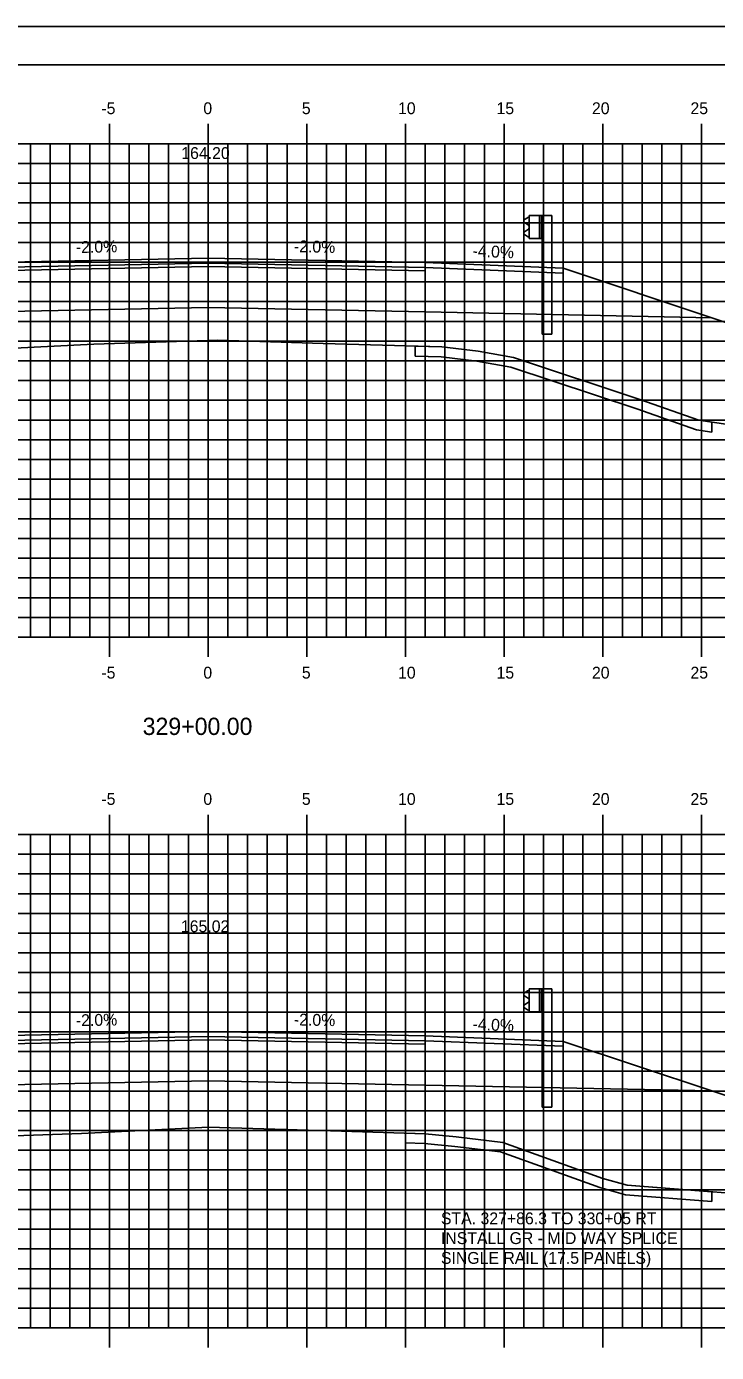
# Model space of a CAD drawing. Extents: x 1140981 to 1141151, y 608981 to 609091.
# Drawn here: x 1141054.6 to 1141089.5, y 609024.1 to 609091.3 of the extents above; entities that cross this region are included whole.
import ezdxf

# ---------------------------------------------------------------- set-up
doc = ezdxf.new("R2010")
doc.units = 0
for name, color, linetype in [('ANNOTATION', 7, 'Continuous'), ('BORDER', 7, 'Continuous'), ('D_Guardrail_Beam_Rt', 7, 'Continuous'), ('D_Guardrail_ConcBarrier', 7, 'Continuous'), ('D_Roadway_Centerline', 7, 'Continuous'), ('D_Roadway_Centerline_Text', 7, 'Continuous'), ('D_Roadway_Edge_Shoulder', 7, 'Continuous'), ('D_Roadway_Edge_TW', 7, 'Continuous'), ('D_Roadway_Pavement', 7, 'Continuous'), ('D_Roadway_SlopeLines', 7, 'Continuous'), ('D_Roadway_SubGrade', 7, 'Continuous'), ('H_V ANNOTATION', 7, 'Continuous'), ('MAJOR', 7, 'Continuous'), ('MINOR', 7, 'Continuous'), ('PLOT BOUNDARY', 7, 'Continuous'), ('S_Roadway_Centerline', 7, 'Continuous'), ('SHADING', 7, 'Continuous')]:
    doc.layers.add(name, color=color, linetype=linetype)

msp = doc.modelspace()

# ---------------------------------------------------------------- linework, layer by layer
for points in [[(1141018.694, 609070.301), (1141034.295, 609075.501), (1141037.295, 609076.501), (1141044.764, 609078.991), (1141044.765, 609078.991), (1141052.758, 609079.311), (1141063.758, 609079.531), (1141074.758, 609079.311), (1141081.758, 609079.031), (1141089.29, 609076.52), (1141092.29, 609075.52), (1141108.295, 609070.185)], [(1141015.324, 609031.014), (1141031.055, 609036.258), (1141034.055, 609037.258), (1141041.302, 609039.673), (1141041.303, 609039.673), (1141052.758, 609040.132), (1141063.758, 609040.352), (1141074.758, 609040.132), (1141081.758, 609039.852), (1141089.29, 609037.341), (1141092.29, 609036.341), (1141104.882, 609032.144)]]:
    msp.add_lwpolyline(points)
at = {"layer": 'BORDER'}
msp.add_lwpolyline([(1140988.758, 608984.335), (1141148.758, 608984.335), (1141148.758, 609089.335), (1140988.758, 609089.335)], close=True, dxfattribs=at)
at = {"layer": 'D_Guardrail_Beam_Rt'}
for p, q in [((1141079.939, 609081.59), (1141079.795, 609081.49)), ((1141079.795, 609081.347), (1141079.99, 609081.21)), ((1141080.029, 609081.611), (1141079.954, 609081.596)), ((1141079.99, 609081.011), (1141079.795, 609080.875)), ((1141079.795, 609080.732), (1141079.939, 609080.632)), ((1141079.954, 609080.626), (1141080.029, 609080.611)), ((1141080.024, 609081.146), (1141080.024, 609081.076)), ((1141079.938, 609042.411), (1141079.795, 609042.311)), ((1141080.028, 609042.432), (1141079.954, 609042.417)), ((1141079.795, 609042.168), (1141079.99, 609042.031)), ((1141079.99, 609041.832), (1141079.795, 609041.696)), ((1141080.024, 609041.967), (1141080.024, 609041.897)), ((1141079.795, 609041.553), (1141079.938, 609041.453)), ((1141079.954, 609041.447), (1141080.028, 609041.432))]:
    msp.add_line(p, q, dxfattribs=at)
for centre, major_axis, start_param, end_param in [((1141079.845, 609081.418), (-0.0877, 0), 5.323254, 7.243116), ((1141079.962, 609081.556), (-0.0417, 0), 4.907132, 5.323254), ((1141079.945, 609081.146), (0.0789, 0), 0, 0.959931), ((1141079.845, 609080.804), (-0.0877, 0), 5.323254, 7.243116), ((1141079.962, 609080.666), (-0.0417, 0), 0.959931, 1.376053), ((1141079.945, 609081.076), (0.0789, 0), 5.323254, 6.283185), ((1141079.845, 609042.239), (-0.0877, 0), 5.323254, 7.243116), ((1141079.962, 609042.377), (-0.0417, 0), 4.907132, 5.323254), ((1141079.845, 609041.625), (-0.0877, 0), 5.323254, 7.243116), ((1141079.945, 609041.967), (0.0789, 0), 0, 0.959931), ((1141079.945, 609041.897), (0.0789, 0), 5.323254, 6.283185), ((1141079.962, 609041.487), (-0.0417, 0), 0.959931, 1.376053)]:
    msp.add_ellipse(centre, major_axis=major_axis, ratio=0.995501, start_param=start_param, end_param=end_param, dxfattribs=at)
at = {"layer": 'D_Guardrail_ConcBarrier'}
for p, q in [((1141080.029, 609081.694), (1141080.716, 609081.694)), ((1141080.029, 609080.528), (1141080.029, 609081.694)), ((1141080.549, 609081.694), (1141080.549, 609080.528)), ((1141080.654, 609081.694), (1141080.654, 609080.528)), ((1141080.716, 609081.694), (1141081.187, 609081.694)), ((1141080.716, 609081.694), (1141080.716, 609080.528)), ((1141081.187, 609081.694), (1141081.187, 609075.694)), ((1141080.716, 609080.528), (1141080.029, 609080.528)), ((1141080.695, 609075.694), (1141080.695, 609080.528)), ((1141080.695, 609075.694), (1141081.187, 609075.694)), ((1141080.028, 609042.515), (1141080.716, 609042.515)), ((1141080.028, 609041.349), (1141080.028, 609042.515)), ((1141080.549, 609042.515), (1141080.549, 609041.349)), ((1141080.653, 609042.515), (1141080.653, 609041.349)), ((1141080.716, 609042.515), (1141081.187, 609042.515)), ((1141080.716, 609042.515), (1141080.716, 609041.349)), ((1141081.187, 609042.515), (1141081.187, 609036.515)), ((1141080.716, 609041.349), (1141080.028, 609041.349)), ((1141080.695, 609036.515), (1141080.695, 609041.349)), ((1141080.695, 609036.515), (1141081.187, 609036.515))]:
    msp.add_line(p, q, dxfattribs=at)
at = {"layer": 'D_Roadway_Edge_Shoulder'}
for points in [[(1141074.758, 609079.311), (1141081.758, 609079.031), (1141081.758, 609078.781), (1141074.758, 609079.061)], [(1141074.758, 609040.132), (1141081.758, 609039.852), (1141081.758, 609039.602), (1141074.758, 609039.882)]]:
    msp.add_lwpolyline(points, close=True, dxfattribs=at)
at = {"layer": 'D_Roadway_Edge_TW'}
for points in [[(1141052.758, 609079.061), (1141052.758, 609079.311), (1141063.758, 609079.531), (1141074.758, 609079.311), (1141074.758, 609079.061), (1141063.758, 609079.281)], [(1141052.758, 609039.882), (1141052.758, 609040.132), (1141063.758, 609040.352), (1141074.758, 609040.132), (1141074.758, 609039.882), (1141063.758, 609040.102)]]:
    msp.add_lwpolyline(points, close=True, dxfattribs=at)
at = {"layer": 'D_Roadway_Pavement'}
for points in [[(1141052.758, 609078.894), (1141052.758, 609079.061), (1141063.758, 609079.281), (1141074.758, 609079.061), (1141074.758, 609078.894), (1141063.758, 609079.114)], [(1141052.758, 609039.715), (1141052.758, 609039.882), (1141063.758, 609040.102), (1141074.758, 609039.882), (1141074.758, 609039.715), (1141063.758, 609039.935)]]:
    msp.add_lwpolyline(points, close=True, dxfattribs=at)
at = {"layer": 'D_Roadway_SlopeLines'}
for p, q in [((1141074.255, 609075.079), (1141074.255, 609074.579)), ((1141089.29, 609071.232), (1141089.29, 609070.727)), ((1141073.758, 609035.204), (1141073.758, 609034.704)), ((1141089.29, 609032.23), (1141089.29, 609031.736))]:
    msp.add_line(p, q, dxfattribs=at)
for points in [[(1141089.29, 609076.52), (1141092.29, 609075.52)], [(1141074.255, 609074.579), (1141075.567, 609074.54), (1141077.372, 609074.326), (1141079.104, 609074.012), (1141085.486, 609071.91), (1141088.511, 609070.842), (1141089.29, 609070.727)], [(1141089.29, 609037.341), (1141092.29, 609036.341)], [(1141073.758, 609034.711), (1141074.732, 609034.681), (1141076.268, 609034.527), (1141078.578, 609034.254), (1141083.608, 609032.442), (1141084.913, 609032.074), (1141089.29, 609031.736)]]:
    msp.add_lwpolyline(points, dxfattribs=at)
at = {"layer": 'D_Roadway_SubGrade'}
for points in [[(1141052.758, 609076.811), (1141052.758, 609078.894), (1141063.758, 609079.114), (1141074.758, 609078.894), (1141074.758, 609076.811), (1141063.758, 609077.031)], [(1141074.758, 609078.894), (1141074.758, 609079.061), (1141081.758, 609078.781), (1141081.758, 609079.031), (1141081.758, 609079.031), (1141089.29, 609076.52), (1141074.758, 609076.811)], [(1141052.758, 609037.632), (1141052.758, 609039.715), (1141063.758, 609039.935), (1141074.758, 609039.715), (1141074.758, 609037.632), (1141063.758, 609037.852)], [(1141074.758, 609039.715), (1141074.758, 609039.882), (1141081.758, 609039.602), (1141081.758, 609039.852), (1141081.758, 609039.852), (1141089.29, 609037.341), (1141074.758, 609037.632)]]:
    msp.add_lwpolyline(points, close=True, dxfattribs=at)
at = {"layer": 'MAJOR'}
for p, q in [((1141058.758, 609086.337), (1141058.758, 609085.335)), ((1141063.758, 609086.337), (1141063.758, 609085.335)), ((1141068.758, 609086.337), (1141068.758, 609085.335)), ((1141073.758, 609086.337), (1141073.758, 609085.335)), ((1141078.758, 609086.337), (1141078.758, 609085.335)), ((1141083.758, 609086.337), (1141083.758, 609085.335)), ((1141088.758, 609086.337), (1141088.758, 609085.335)), ((1140993.758, 609085.335), (1141133.758, 609085.335)), ((1140993.758, 609085.335), (1141133.758, 609085.335)), ((1141058.758, 609060.335), (1141058.758, 609085.335)), ((1141063.758, 609060.335), (1141063.758, 609085.335)), ((1141068.758, 609060.335), (1141068.758, 609085.335)), ((1141073.758, 609060.335), (1141073.758, 609085.335)), ((1141078.758, 609060.335), (1141078.758, 609085.335)), ((1141083.758, 609060.335), (1141083.758, 609085.335)), ((1141088.758, 609060.335), (1141088.758, 609085.335)), ((1140993.758, 609080.335), (1141133.758, 609080.335)), ((1140993.758, 609075.335), (1141133.758, 609075.335)), ((1140993.758, 609070.335), (1141133.758, 609070.335)), ((1140993.758, 609065.335), (1141133.758, 609065.335)), ((1140993.758, 609060.335), (1141133.758, 609060.335)), ((1140993.758, 609060.335), (1141133.758, 609060.335)), ((1141058.758, 609059.333), (1141058.758, 609060.335)), ((1141063.758, 609059.333), (1141063.758, 609060.335)), ((1141068.758, 609059.333), (1141068.758, 609060.335)), ((1141073.758, 609059.333), (1141073.758, 609060.335)), ((1141078.758, 609059.333), (1141078.758, 609060.335)), ((1141083.758, 609059.333), (1141083.758, 609060.335)), ((1141088.758, 609059.333), (1141088.758, 609060.335)), ((1141058.758, 609051.337), (1141058.758, 609050.335)), ((1141063.758, 609051.337), (1141063.758, 609050.335)), ((1141068.758, 609051.337), (1141068.758, 609050.335)), ((1141073.758, 609051.337), (1141073.758, 609050.335)), ((1141078.758, 609051.337), (1141078.758, 609050.335)), ((1141083.758, 609051.337), (1141083.758, 609050.335)), ((1141088.758, 609051.337), (1141088.758, 609050.335)), ((1140993.758, 609050.335), (1141133.758, 609050.335)), ((1140993.758, 609050.335), (1141133.758, 609050.335)), ((1141058.758, 609025.335), (1141058.758, 609050.335)), ((1141063.758, 609025.335), (1141063.758, 609050.335)), ((1141068.758, 609025.335), (1141068.758, 609050.335)), ((1141073.758, 609025.335), (1141073.758, 609050.335)), ((1141078.758, 609025.335), (1141078.758, 609050.335)), ((1141083.758, 609025.335), (1141083.758, 609050.335)), ((1141088.758, 609025.335), (1141088.758, 609050.335)), ((1140993.758, 609045.335), (1141133.758, 609045.335)), ((1140993.758, 609040.335), (1141133.758, 609040.335)), ((1140993.758, 609035.335), (1141133.758, 609035.335)), ((1140993.758, 609030.335), (1141133.758, 609030.335)), ((1140993.758, 609025.335), (1141133.758, 609025.335)), ((1140993.758, 609025.335), (1141133.758, 609025.335)), ((1141058.758, 609024.333), (1141058.758, 609025.335)), ((1141063.758, 609024.333), (1141063.758, 609025.335)), ((1141068.758, 609024.333), (1141068.758, 609025.335)), ((1141073.758, 609024.333), (1141073.758, 609025.335)), ((1141078.758, 609024.333), (1141078.758, 609025.335)), ((1141083.758, 609024.333), (1141083.758, 609025.335)), ((1141088.758, 609024.333), (1141088.758, 609025.335))]:
    msp.add_line(p, q, dxfattribs=at)
at = {"layer": 'MINOR'}
for p, q in [((1141054.758, 609060.335), (1141054.758, 609085.335)), ((1141055.758, 609060.335), (1141055.758, 609085.335)), ((1141056.758, 609060.335), (1141056.758, 609085.335)), ((1141057.758, 609060.335), (1141057.758, 609085.335)), ((1141059.758, 609060.335), (1141059.758, 609085.335)), ((1141060.758, 609060.335), (1141060.758, 609085.335)), ((1141061.758, 609060.335), (1141061.758, 609085.335)), ((1141062.758, 609060.335), (1141062.758, 609085.335)), ((1141064.758, 609060.335), (1141064.758, 609085.335)), ((1141065.758, 609060.335), (1141065.758, 609085.335)), ((1141066.758, 609060.335), (1141066.758, 609085.335)), ((1141067.758, 609060.335), (1141067.758, 609085.335)), ((1141069.758, 609060.335), (1141069.758, 609085.335)), ((1141070.758, 609060.335), (1141070.758, 609085.335)), ((1141071.758, 609060.335), (1141071.758, 609085.335)), ((1141072.758, 609060.335), (1141072.758, 609085.335)), ((1141074.758, 609060.335), (1141074.758, 609085.335)), ((1141075.758, 609060.335), (1141075.758, 609085.335)), ((1141076.758, 609060.335), (1141076.758, 609085.335)), ((1141077.758, 609060.335), (1141077.758, 609085.335)), ((1141079.758, 609060.335), (1141079.758, 609085.335)), ((1141080.758, 609060.335), (1141080.758, 609085.335)), ((1141081.758, 609060.335), (1141081.758, 609085.335)), ((1141082.758, 609060.335), (1141082.758, 609085.335)), ((1141084.758, 609060.335), (1141084.758, 609085.335)), ((1141085.758, 609060.335), (1141085.758, 609085.335)), ((1141086.758, 609060.335), (1141086.758, 609085.335)), ((1141087.758, 609060.335), (1141087.758, 609085.335)), ((1140993.758, 609084.335), (1141133.758, 609084.335)), ((1140993.758, 609083.335), (1141133.758, 609083.335)), ((1140993.758, 609082.335), (1141133.758, 609082.335)), ((1140993.758, 609081.335), (1141133.758, 609081.335)), ((1140993.758, 609079.335), (1141133.758, 609079.335)), ((1140993.758, 609078.335), (1141133.758, 609078.335)), ((1140993.758, 609077.335), (1141133.758, 609077.335)), ((1140993.758, 609076.335), (1141133.758, 609076.335)), ((1140993.758, 609074.335), (1141133.758, 609074.335)), ((1140993.758, 609073.335), (1141133.758, 609073.335)), ((1140993.758, 609072.335), (1141133.758, 609072.335)), ((1140993.758, 609071.335), (1141133.758, 609071.335)), ((1140993.758, 609069.335), (1141133.758, 609069.335)), ((1140993.758, 609068.335), (1141133.758, 609068.335)), ((1140993.758, 609067.335), (1141133.758, 609067.335)), ((1140993.758, 609066.335), (1141133.758, 609066.335)), ((1140993.758, 609064.335), (1141133.758, 609064.335)), ((1140993.758, 609063.335), (1141133.758, 609063.335)), ((1140993.758, 609062.335), (1141133.758, 609062.335)), ((1140993.758, 609061.335), (1141133.758, 609061.335)), ((1141054.758, 609025.335), (1141054.758, 609050.335)), ((1141055.758, 609025.335), (1141055.758, 609050.335)), ((1141056.758, 609025.335), (1141056.758, 609050.335)), ((1141057.758, 609025.335), (1141057.758, 609050.335)), ((1141059.758, 609025.335), (1141059.758, 609050.335)), ((1141060.758, 609025.335), (1141060.758, 609050.335)), ((1141061.758, 609025.335), (1141061.758, 609050.335)), ((1141062.758, 609025.335), (1141062.758, 609050.335)), ((1141064.758, 609025.335), (1141064.758, 609050.335)), ((1141065.758, 609025.335), (1141065.758, 609050.335)), ((1141066.758, 609025.335), (1141066.758, 609050.335)), ((1141067.758, 609025.335), (1141067.758, 609050.335)), ((1141069.758, 609025.335), (1141069.758, 609050.335)), ((1141070.758, 609025.335), (1141070.758, 609050.335)), ((1141071.758, 609025.335), (1141071.758, 609050.335)), ((1141072.758, 609025.335), (1141072.758, 609050.335)), ((1141074.758, 609025.335), (1141074.758, 609050.335)), ((1141075.758, 609025.335), (1141075.758, 609050.335)), ((1141076.758, 609025.335), (1141076.758, 609050.335)), ((1141077.758, 609025.335), (1141077.758, 609050.335)), ((1141079.758, 609025.335), (1141079.758, 609050.335)), ((1141080.758, 609025.335), (1141080.758, 609050.335)), ((1141081.758, 609025.335), (1141081.758, 609050.335)), ((1141082.758, 609025.335), (1141082.758, 609050.335)), ((1141084.758, 609025.335), (1141084.758, 609050.335)), ((1141085.758, 609025.335), (1141085.758, 609050.335)), ((1141086.758, 609025.335), (1141086.758, 609050.335)), ((1141087.758, 609025.335), (1141087.758, 609050.335)), ((1140993.758, 609049.335), (1141133.758, 609049.335)), ((1140993.758, 609048.335), (1141133.758, 609048.335)), ((1140993.758, 609047.335), (1141133.758, 609047.335)), ((1140993.758, 609046.335), (1141133.758, 609046.335)), ((1140993.758, 609044.335), (1141133.758, 609044.335)), ((1140993.758, 609043.335), (1141133.758, 609043.335)), ((1140993.758, 609042.335), (1141133.758, 609042.335)), ((1140993.758, 609041.335), (1141133.758, 609041.335)), ((1140993.758, 609039.335), (1141133.758, 609039.335)), ((1140993.758, 609038.335), (1141133.758, 609038.335)), ((1140993.758, 609037.335), (1141133.758, 609037.335)), ((1140993.758, 609036.335), (1141133.758, 609036.335)), ((1140993.758, 609034.335), (1141133.758, 609034.335)), ((1140993.758, 609033.335), (1141133.758, 609033.335)), ((1140993.758, 609032.335), (1141133.758, 609032.335)), ((1140993.758, 609031.335), (1141133.758, 609031.335)), ((1140993.758, 609029.335), (1141133.758, 609029.335)), ((1140993.758, 609028.335), (1141133.758, 609028.335)), ((1140993.758, 609027.335), (1141133.758, 609027.335)), ((1140993.758, 609026.335), (1141133.758, 609026.335))]:
    msp.add_line(p, q, dxfattribs=at)
at = {"layer": 'PLOT BOUNDARY'}
msp.add_lwpolyline([(1140980.664, 608981.276), (1141150.664, 608981.276), (1141150.664, 609091.276), (1140980.664, 609091.276)], close=True, dxfattribs=at)
at = {"layer": 'S_Roadway_Centerline'}
for points in [[(1140993.758, 609070.235), (1141016.927, 609070.323), (1141025.835, 609070.211), (1141031.23, 609070.816), (1141045.025, 609071.913), (1141046.887, 609072.758), (1141050.236, 609074.313), (1141052.144, 609074.689), (1141053.6, 609074.965), (1141057.959, 609075.178), (1141064.255, 609075.378), (1141069.594, 609075.216), (1141075.604, 609075.039), (1141077.446, 609074.821), (1141079.228, 609074.497), (1141085.647, 609072.383), (1141088.632, 609071.329), (1141093.986, 609070.537), (1141096.999, 609070.318), (1141110.65, 609070.157), (1141115.506, 609070.212)], [(1140993.758, 609030.733), (1141009.977, 609030.874), (1141026.763, 609031.313), (1141030.432, 609031.56), (1141045.208, 609032.752), (1141047.834, 609033.947), (1141049.661, 609034.555), (1141051.778, 609034.94), (1141052.932, 609035.025), (1141057.344, 609035.19), (1141063.779, 609035.507), (1141070.513, 609035.304), (1141074.764, 609035.173), (1141076.322, 609035.016), (1141078.692, 609034.736), (1141083.759, 609032.911), (1141084.999, 609032.561), (1141091.498, 609032.059), (1141093.213, 609032.024), (1141099.245, 609031.951), (1141112.53, 609032.405)]]:
    msp.add_lwpolyline(points, dxfattribs=at)
at = {"layer": 'SHADING'}
for p, q in [((1141074.255, 609075.079), (1141074.255, 609074.579)), ((1141089.29, 609071.232), (1141088.632, 609071.329)), ((1141089.29, 609070.727), (1141089.29, 609071.232)), ((1141073.758, 609035.204), (1141073.758, 609034.704)), ((1141089.29, 609032.23), (1141084.999, 609032.561)), ((1141089.29, 609031.736), (1141089.29, 609032.23))]:
    msp.add_line(p, q, dxfattribs=at)
for points in [[(1141088.632, 609071.329), (1141085.647, 609072.383), (1141079.228, 609074.497), (1141077.446, 609074.821), (1141075.604, 609075.039), (1141074.255, 609075.079)], [(1141074.255, 609074.579), (1141075.567, 609074.54), (1141077.372, 609074.326), (1141079.104, 609074.012), (1141085.486, 609071.91), (1141088.511, 609070.842), (1141089.29, 609070.727)], [(1141084.999, 609032.561), (1141083.759, 609032.911), (1141078.692, 609034.736), (1141076.322, 609035.016), (1141074.764, 609035.173), (1141073.758, 609035.204)], [(1141073.758, 609034.704), (1141074.732, 609034.681), (1141076.268, 609034.527), (1141078.578, 609034.254), (1141083.608, 609032.442), (1141084.913, 609032.074), (1141089.29, 609031.736)]]:
    msp.add_lwpolyline(points, dxfattribs=at)

# ---------------------------------------------------------------- texts
at = {"layer": 'ANNOTATION'}
for s, rotation, p in [('-2.0%', 1.14576, (1141057.061, 609079.797)), ('-2.0%', 358.85424, (1141068.101, 609079.844)), ('-4.0%', 357.70939, (1141077.153, 609079.616)), ('-2.0%', 1.14576, (1141057.061, 609040.618)), ('-2.0%', 358.85424, (1141068.101, 609040.665)), ('-4.0%', 357.70939, (1141077.153, 609040.437))]:
    msp.add_text(s, height=0.6, rotation=rotation, dxfattribs=at).set_placement(p)
for s, p in [('STA. 327+86.3 TO 330+05 RT', (1141075.557, 609030.584)), ('INSTALL GR - MID WAY SPLICE', (1141075.557, 609029.582)), ('SINGLE RAIL (17.5 PANELS)', (1141075.557, 609028.58))]:
    msp.add_text(s, height=0.6, dxfattribs=at).set_placement(p)
at = {"layer": 'D_Roadway_Centerline'}
for s, p in [('C', (1141063.752, 609079.531)), ('C', (1141063.752, 609079.531)), ('L', (1141063.758, 609079.523)), ('L', (1141063.758, 609079.523)), ('C', (1141063.752, 609040.352)), ('C', (1141063.752, 609040.352)), ('L', (1141063.758, 609040.344)), ('L', (1141063.758, 609040.344))]:
    msp.add_text(s, height=0.0146, dxfattribs=at).set_placement(p)
at = {"layer": 'D_Roadway_Centerline_Text'}
for s, p in [('164.20', (1141062.399, 609084.563)), ('165.02', (1141062.38, 609045.384))]:
    msp.add_text(s, height=0.6, dxfattribs=at).set_placement(p)
at = {"layer": 'H_V ANNOTATION'}
for s, height, p in [('-5', 0.6, (1141058.348, 609086.835)), ('0', 0.6, (1141063.517, 609086.835)), ('5', 0.6, (1141068.509, 609086.835)), ('10', 0.6, (1141073.383, 609086.835)), ('15', 0.6, (1141078.375, 609086.835)), ('20', 0.6, (1141083.212, 609086.835)), ('25', 0.6, (1141088.204, 609086.835)), ('-5', 0.6, (1141058.348, 609058.235)), ('0', 0.6, (1141063.517, 609058.235)), ('5', 0.6, (1141068.509, 609058.235)), ('10', 0.6, (1141073.383, 609058.235)), ('15', 0.6, (1141078.375, 609058.235)), ('20', 0.6, (1141083.212, 609058.235)), ('25', 0.6, (1141088.204, 609058.235)), ('329+00.00', 0.875, (1141060.441, 609055.378)), ('-5', 0.6, (1141058.348, 609051.835)), ('0', 0.6, (1141063.517, 609051.835)), ('5', 0.6, (1141068.509, 609051.835)), ('10', 0.6, (1141073.383, 609051.835)), ('15', 0.6, (1141078.375, 609051.835)), ('20', 0.6, (1141083.212, 609051.835)), ('25', 0.6, (1141088.204, 609051.835))]:
    msp.add_text(s, height=height, dxfattribs=at).set_placement(p)
at = {"layer": 'S_Roadway_Centerline'}
for s, p in [('C', (1141064.25, 609075.378)), ('L', (1141064.255, 609075.371)), ('C', (1141063.774, 609035.507)), ('L', (1141063.779, 609035.5))]:
    msp.add_text(s, height=0.0146, dxfattribs=at).set_placement(p)

doc.saveas('drawing.dxf')
